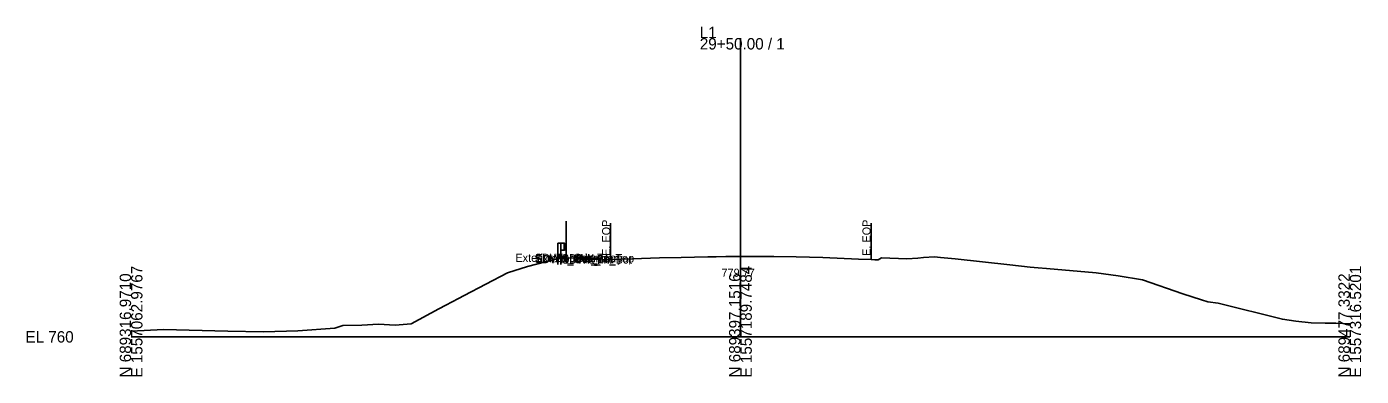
# Model space of a CAD drawing. Extents: x -26 to 2603, y -3010 to 9589.
# Drawn here: x 974.3 to 1302.8, y 2990.3 to 3076.3 of the extents above; entities that cross this region are included whole.
import ezdxf

# ---------------------------------------------------------------- set-up
doc = ezdxf.new("R2010")
doc.units = 0
for name, color, linetype in [('Default', 7, 'Continuous'), ('Exist Cross Section Cell', 7, 'Continuous'), ('Exist XS Center Line Elevation Label', 7, 'Continuous'), ('Exist XS Ground Line', 7, 'Continuous'), ('Prop CMT Conc Surface', 7, 'Continuous'), ('Prop CMT Concrete Structures', 7, 'Continuous'), ('Prop CMT Slope Grass', 7, 'Continuous'), ('Prop XS Earthwork Shape', 7, 'Continuous'), ('Prop XS Label Text', 7, 'Continuous'), ('Scratch_Level_1', 7, 'Continuous'), ('Typical Guardrail CELL', 7, 'Continuous')]:
    doc.layers.add(name, color=color, linetype=linetype)

msp = doc.modelspace()

# ---------------------------------------------------------------- linework, layer by layer
at = {"layer": 'Exist Cross Section Cell'}
for p, q in [((1150, 3000), (1150, 3073.46)), ((1000, 3000), (1150, 3000)), ((1150, 3000), (1300, 3000))]:
    msp.add_line(p, q, dxfattribs=at)
at = {"layer": 'Exist XS Ground Line'}
msp.add_lwpolyline([(1000, 3001.43), (1007.99, 3001.8), (1023.84, 3001.38), (1032.61, 3001.21), (1041.05, 3001.46), (1050.2, 3002.14), (1052.1, 3002.8), (1056.78, 3002.88), (1060.91, 3003.11), (1065.05, 3002.91), (1067.97, 3003.12), (1068.93, 3003.17), (1075.76, 3006.92), (1077.46, 3007.81), (1080.6, 3009.41), (1082.01, 3010.19), (1092.67, 3015.73), (1097.61, 3017.34), (1106.08, 3019.52), (1108.27, 3019.34), (1109.82, 3019.41), (1111.22, 3019.55), (1111.62, 3019.51), (1112.41, 3019.38), (1115.49, 3019.34), (1116.1, 3018.9), (1117.01, 3018.93), (1118.05, 3018.99), (1123.46, 3019.16), (1130.04, 3019.41), (1135.44, 3019.5), (1141.96, 3019.65), (1143.99, 3019.68), (1146.43, 3019.73), (1149.21, 3019.76), (1150, 3019.77), (1151.39, 3019.79), (1154.54, 3019.76), (1158.24, 3019.74), (1163.72, 3019.65), (1170.25, 3019.53), (1179.06, 3019.14), (1182.15, 3018.99), (1183.07, 3018.97), (1183.88, 3018.95), (1184.28, 3019.16), (1184.72, 3019.4), (1190.97, 3019.18), (1193.69, 3019.31), (1195.05, 3019.48), (1197.78, 3019.7), (1199.24, 3019.54), (1202.86, 3019.15), (1216.29, 3017.72), (1221.33, 3017.14), (1223.27, 3017), (1225.31, 3016.8), (1237.55, 3015.71), (1242.95, 3015), (1248.95, 3014.04), (1258.89, 3010.61), (1263.47, 3009.14), (1265.1, 3008.65), (1267.64, 3008.25), (1283.43, 3004.32), (1286.72, 3003.84), (1290.46, 3003.45), (1293.98, 3003.39), (1296.59, 3003.36), (1300, 3003.22)], dxfattribs=at)
at = {"layer": 'Prop CMT Conc Surface'}
msp.add_lwpolyline([(1115.46, 3019.34), (1110.46, 3019.44)], dxfattribs=at)
at = {"layer": 'Prop CMT Concrete Structures'}
for points in [[(1110.46, 3019.11), (1110.46, 3019.44)], [(1110.46, 3019.44), (1115.46, 3019.34)], [(1115.46, 3019.34), (1115.46, 3019.01)], [(1115.46, 3019.01), (1110.46, 3019.11)]]:
    msp.add_lwpolyline(points, dxfattribs=at)
at = {"layer": 'Prop CMT Slope Grass'}
msp.add_line((1110.46, 3019.44), (1110.16, 3019.45), dxfattribs=at)
at = {"layer": 'Prop XS Earthwork Shape'}
for points in [[(1110.46, 3019.44), (1110.16, 3019.45), (1111.22, 3019.55), (1111.62, 3019.51), (1112.27, 3019.4)], [(1112.41, 3019.38), (1115.46, 3019.34), (1115.46, 3019.01), (1110.46, 3019.11), (1110.46, 3019.44), (1112.27, 3019.4)]]:
    msp.add_lwpolyline(points, close=True, dxfattribs=at)
at = {"layer": 'Prop XS Label Text'}
for p, q in [((1118.05, 3027.99), (1118.05, 3018.99)), ((1182.15, 3027.99), (1182.15, 3018.99))]:
    msp.add_line(p, q, dxfattribs=at)
at = {"layer": 'Scratch_Level_1'}
msp.add_line((1107.07, 3018.6), (1107.07, 3028.43), dxfattribs=at)
at = {"layer": 'Typical Guardrail CELL'}
for p, q in [((1105.83, 3023.02), (1105.09, 3023.02)), ((1105.09, 3023.02), (1105.09, 3019.3)), ((1105.83, 3023.02), (1105.83, 3019.3)), ((1105.83, 3023.02), (1106.58, 3023.02)), ((1106.58, 3023.02), (1106.58, 3021.28)), ((1106.58, 3023.02), (1107.01, 3022.72)), ((1106.58, 3022.22), (1107.01, 3022.53)), ((1105.83, 3019.3), (1105.09, 3019.3)), ((1105.09, 3019.3), (1105.09, 3017.78)), ((1105.83, 3021.28), (1106.58, 3021.28)), ((1105.83, 3019.3), (1105.83, 3017.78)), ((1106.58, 3022.15), (1106.58, 3022.22)), ((1106.58, 3022.15), (1106.58, 3022.08)), ((1106.58, 3022.08), (1107.01, 3021.78)), ((1106.58, 3021.28), (1107.01, 3021.59))]:
    msp.add_line(p, q, dxfattribs=at)
for centre, start, end in [((1106.95, 3022.62), 304.9888, 54.997), ((1106.95, 3021.68), 304.9634, 54.9941)]:
    msp.add_arc(centre, 0.116, start, end, dxfattribs=at)

# ---------------------------------------------------------------- texts
at = {"layer": 'Default'}
for s, height, p in [('Exterior Boundary', 2, (1094.61, 3018.44)), ('SDWK_Out_Top', 2, (1099.39, 3018.44)), ('SDWK_Out_Bot', 2, (1099.42, 3018.11)), ('Exterior Boundary', 2, (1099.61, 3018.34)), ('SDWK_In_Top', 2, (1106.01, 3018.34)), ('SDWK_In_Bot', 2, (1106.05, 3018.01)), ('-', 0.0001, (1000, 3000))]:
    msp.add_text(s, height=height, dxfattribs=at).set_placement(p)
at = {"layer": 'Exist Cross Section Cell'}
for s, p in [('L1', (1140, 3073.46)), ('29+50.00 / 1', (1140, 3070.66)), ('EL 760', (974, 2998.6))]:
    msp.add_text(s, height=2.8, dxfattribs=at).set_placement(p)
for s, p in [('E 1557062.9767', (1002.8, 2990)), ('E 1557189.7484', (1152.8, 2990)), ('E 1557316.5201', (1302.8, 2990)), ('N 689316.9710', (1000, 2990)), ('N 689397.1516', (1150, 2990)), ('N 689477.3322', (1300, 2990))]:
    msp.add_text(s, height=2.8, rotation=90, dxfattribs=at).set_placement(p)
at = {"layer": 'Exist XS Center Line Elevation Label'}
msp.add_text('779.77', height=2, dxfattribs=at).set_placement((1145.35, 3014.77))
at = {"layer": 'Prop XS Label Text'}
for p in [(1117.95, 3019.91), (1182.05, 3019.92)]:
    msp.add_text('E. EOP', height=2, rotation=90, dxfattribs=at).set_placement(p)

doc.saveas('drawing.dxf')
